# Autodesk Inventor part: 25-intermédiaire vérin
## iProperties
Created: 2011-02
Part Number: 25-intermédiaire vérin
Document SubType Name: Modeling
Designer: eric
Density: 1 g/cm^3
Author: eric
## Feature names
1. Base1
